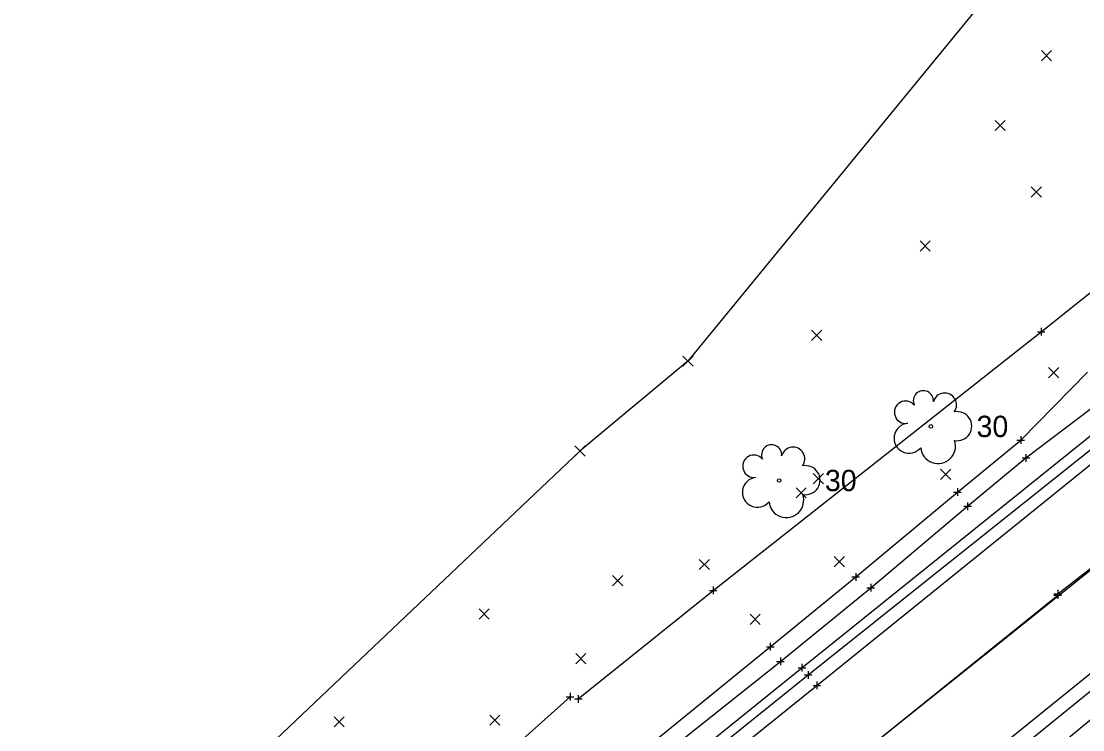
# Model space of a CAD drawing. Extents: x 2184635 to 2185378, y 369880 to 370486.
# Drawn here: x 2184636.1 to 2184775.4, y 369980.5 to 370073.5 of the extents above; entities that cross this region are included whole.
import ezdxf

# ---------------------------------------------------------------- set-up
doc = ezdxf.new("R2010")
doc.units = 0
for name, color, linetype in [('_CIVIL_CONSTRUCTION', 7, 'Continuous'), ('DR_X_Ditch', 7, 'Continuous'), ('GE_X_Alignment', 7, 'Continuous'), ('GE_X_Alignment_100_Distances', 7, 'Continuous'), ('PM_X_CL_Double_Solid', 7, 'Continuous'), ('PM_X_CL_Pass_Proh_Lt', 7, 'Continuous'), ('PM_X_CL_Pass_Proh_Rt', 7, 'Continuous'), ('PM_X_Edge_Line', 7, 'Continuous'), ('PV_X_COP', 7, 'Continuous'), ('PV_X_EOP', 7, 'Continuous'), ('PV_X_Shoulder', 7, 'Continuous'), ('RD_X_Fence', 7, 'Continuous'), ('RD_X_Gate', 7, 'Continuous'), ('RW_X_CL', 7, 'Continuous'), ('SV_X_Break_Lines', 7, 'Continuous'), ('SV_X_Terrain_Boundary', 7, 'Continuous'), ('VG_X_Text', 7, 'Continuous')]:
    doc.layers.add(name, color=color, linetype=linetype)

msp = doc.modelspace()

# ---------------------------------------------------------------- linework, layer by layer
at = {"layer": '_CIVIL_CONSTRUCTION'}
for p, q in [((2184769.93, 370068.28), (2184771.26, 370069.62)), ((2184769.93, 370069.62), (2184771.26, 370068.28)), ((2184763.84, 370059.12), (2184765.18, 370060.46)), ((2184763.84, 370060.46), (2184765.18, 370059.12)), ((2184768.6, 370050.39), (2184769.94, 370051.73)), ((2184768.6, 370051.73), (2184769.94, 370050.39)), ((2184754.01, 370043.31), (2184755.34, 370044.65)), ((2184754.01, 370044.65), (2184755.34, 370043.31)), ((2184739.77, 370031.58), (2184741.1, 370032.91)), ((2184739.77, 370032.91), (2184741.1, 370031.58)), ((2184722.88, 370028.2), (2184724.22, 370029.54)), ((2184722.88, 370029.54), (2184724.22, 370028.2)), ((2184770.88, 370026.69), (2184772.21, 370028.02)), ((2184770.88, 370028.02), (2184772.21, 370026.69)), ((2184708.73, 370016.41), (2184710.07, 370017.75)), ((2184708.73, 370017.75), (2184710.07, 370016.41)), ((2184739.99, 370012.78), (2184741.32, 370014.11)), ((2184739.99, 370014.11), (2184741.32, 370012.78)), ((2184756.69, 370013.35), (2184758.03, 370014.69)), ((2184756.69, 370014.69), (2184758.03, 370013.35)), ((2184737.73, 370010.91), (2184739.06, 370012.24)), ((2184737.73, 370012.24), (2184739.06, 370010.91)), ((2184725.03, 370001.51), (2184726.36, 370002.85)), ((2184725.03, 370002.85), (2184726.36, 370001.51)), ((2184742.74, 370001.89), (2184744.08, 370003.23)), ((2184742.74, 370003.23), (2184744.08, 370001.89)), ((2184713.66, 369999.39), (2184715, 370000.72)), ((2184713.66, 370000.72), (2184715, 369999.39)), ((2184696.14, 369995.01), (2184697.48, 369996.35)), ((2184696.14, 369996.35), (2184697.48, 369995.01)), ((2184731.71, 369994.3), (2184733.04, 369995.64)), ((2184731.71, 369995.64), (2184733.04, 369994.3)), ((2184708.82, 369989.14), (2184710.16, 369990.48)), ((2184708.82, 369990.48), (2184710.16, 369989.14)), ((2184677.12, 369980.85), (2184678.46, 369982.18)), ((2184677.12, 369982.18), (2184678.46, 369980.85)), ((2184697.55, 369981.08), (2184698.88, 369982.42)), ((2184697.55, 369982.42), (2184698.88, 369981.08))]:
    msp.add_line(p, q, dxfattribs=at)
at = {"layer": 'DR_X_Ditch'}
msp.add_lwpolyline([(2184660, 369928.7), (2184683.17, 369946.52), (2184697.64, 369958.49), (2184716.07, 369973.83), (2184735.69, 369989.46), (2184747.53, 369999.12), (2184760.24, 370009.81), (2184767.89, 370016.17), (2184779.93, 370025.29), (2184787.42, 370032.35)], dxfattribs=at)
at = {"layer": 'GE_X_Alignment'}
for centre in [(2184755.42, 370020.3), (2184735.52, 370013.2)]:
    msp.add_circle(centre, 0.24, dxfattribs=at)
for centre, radius, start, end in [((2184754.44, 370023.67), 1.32, 354.0047, 205.9741), ((2184752.11, 370022.16), 1.47, 39.0625, 279.5412), ((2184757.25, 370023.13), 1.55, 323.83, 165.0376), ((2184758.88, 370020.33), 1.91, 259.1453, 101.4596), ((2184752.57, 370018.75), 1.97, 96.1722, 320.5737), ((2184756.37, 370017.69), 2.28, 184.9476, 19.4572), ((2184734.53, 370016.57), 1.32, 354.0047, 205.9741), ((2184737.34, 370016.03), 1.55, 323.83, 165.0376), ((2184732.21, 370015.07), 1.47, 39.0625, 279.5412), ((2184738.98, 370013.24), 1.91, 259.1453, 101.4596), ((2184732.67, 370011.65), 1.97, 96.1722, 320.5737), ((2184736.46, 370010.6), 2.28, 184.9476, 19.4572)]:
    msp.add_arc(centre, radius, start, end, dxfattribs=at)
at = {"layer": 'GE_X_Alignment_100_Distances'}
for points in [[(2185264.32, 370371.31), (2185225.67, 370339.84), (2185186.92, 370307.74), (2185148.74, 370277.09), (2185109.07, 370245.72), (2185070.47, 370214.75), (2185031.04, 370183.42), (2184991.95, 370153.14), (2184952.24, 370122.38), (2184912.89, 370091.69), (2184876.6, 370062.99), (2184874.53, 370062.2), (2184872.48, 370060.47), (2184871.45, 370058.82), (2184869.46, 370057.79), (2184834.83, 370028.95), (2184796.15, 369998.17), (2184773.73, 369979.62), (2184757.69, 369965.83), (2184717.28, 369935.85), (2184678.36, 369904.18)], [(2184659.61, 369925.95), (2184700.37, 369957.79), (2184738.5, 369988.63), (2184777.83, 370020.25), (2184816.43, 370051.35), (2184855.55, 370082.58), (2184897, 370115.36), (2184935.6, 370145.23), (2184944.92, 370153.84), (2184957.87, 370164.57), (2184961.94, 370169.28), (2184974.73, 370179.72), (2184983.89, 370187.22), (2184992.5, 370194.66), (2184997.57, 370200.25)]]:
    msp.add_lwpolyline(points, dxfattribs=at)
at = {"layer": 'PM_X_CL_Double_Solid'}
msp.add_lwpolyline([(2184667.89, 369914.6), (2184708.44, 369946.75), (2184746.44, 369977.52), (2184772.08, 369998.17)], dxfattribs=at)
at = {"layer": 'PM_X_CL_Pass_Proh_Lt'}
msp.add_lwpolyline([(2185262.14, 370374.2), (2185223.7, 370342.03), (2185185.18, 370310.66), (2185146.68, 370279.54), (2185107.74, 370248.35), (2185068.5, 370216.96), (2185029.05, 370186.04), (2184989.47, 370156.28), (2184949.89, 370125.37), (2184910.77, 370094.56), (2184870.98, 370063.53), (2184832.08, 370032.4), (2184793.2, 370001.49), (2184754.34, 369970.02), (2184715.12, 369938.51), (2184676.14, 369907.22)], dxfattribs=at)
at = {"layer": 'PM_X_CL_Pass_Proh_Rt'}
msp.add_lwpolyline([(2184772.08, 369998.33), (2184786.36, 370009.44), (2184824.96, 370040.26), (2184864.24, 370071.89), (2184905.97, 370104.8), (2184943.4, 370134), (2184983.48, 370165.21), (2185020.26, 370194.47), (2185061.22, 370226.63), (2185099.74, 370257.78), (2185139.18, 370289.51), (2185177.35, 370320.31), (2185216.05, 370351.8), (2185254.73, 370383.45)], dxfattribs=at)
at = {"layer": 'PM_X_Edge_Line'}
msp.add_lwpolyline([(2184661.52, 369922.95), (2184702.12, 369955.42), (2184740.46, 369986.31), (2184779.79, 370018.04), (2184818.42, 370048.83), (2184857.46, 370080.19), (2184899.14, 370112.8), (2184937.36, 370142.73), (2184976.78, 370173.64), (2185013.23, 370203.93), (2185054.74, 370235.21), (2185093.13, 370266.2), (2185132.9, 370298.21), (2185170.88, 370328.99), (2185209.71, 370360.44), (2185248.24, 370392.05)], dxfattribs=at)
at = {"layer": 'PV_X_COP'}
msp.add_lwpolyline([(2184667.94, 369914.54), (2184708.44, 369946.75), (2184746.44, 369977.52), (2184786.36, 370009.44), (2184824.96, 370040.26), (2184864.24, 370071.89), (2184905.97, 370104.8), (2184943.4, 370134), (2184983.48, 370165.21), (2185020.26, 370194.47), (2185061.22, 370226.63), (2185099.74, 370257.78), (2185139.18, 370289.51), (2185177.35, 370320.31), (2185216.05, 370351.8), (2185254.68, 370383.2)], dxfattribs=at)
at = {"layer": 'PV_X_EOP'}
for points in [[(2184661.56, 369922.86), (2184702.12, 369955.42), (2184740.46, 369986.31), (2184779.79, 370018.04), (2184818.42, 370048.83), (2184857.46, 370080.19), (2184899.14, 370112.8), (2184937.36, 370142.73), (2184976.78, 370173.64), (2185013.23, 370203.93), (2185054.74, 370235.21), (2185093.13, 370266.2), (2185132.9, 370298.21), (2185170.88, 370328.99), (2185209.71, 370360.44), (2185248.18, 370392.04)], [(2185262.15, 370374.26), (2185223.7, 370342.03), (2185185.18, 370310.66), (2185146.68, 370279.54), (2185107.74, 370248.35), (2185068.5, 370216.96), (2185029.05, 370186.04), (2184989.47, 370156.28), (2184949.89, 370125.37), (2184910.77, 370094.56), (2184870.98, 370063.53), (2184832.08, 370032.4), (2184793.2, 370001.49), (2184754.34, 369970.02), (2184715.12, 369938.51), (2184676.22, 369907.13)]]:
    msp.add_lwpolyline(points, dxfattribs=at)
at = {"layer": 'PV_X_Shoulder'}
for points in [[(2184660.62, 369924.65), (2184701.18, 369956.99), (2184739.31, 369987.69), (2184778.66, 370019.08), (2184817.14, 370050.2), (2184856.42, 370081.4), (2184897.96, 370114.28), (2184936.32, 370143.73), (2184975.81, 370174.82), (2184986.61, 370184.31), (2184994.08, 370192.55), (2185011.04, 370206.65), (2185033.17, 370224.29), (2185051.81, 370238.9), (2185062.89, 370246.96), (2185064.96, 370248), (2185067.33, 370248.11), (2185092.06, 370267.24), (2185132, 370299.51), (2185169.97, 370330.25), (2185208.84, 370361.61), (2185247.24, 370392.98)], [(2185263.13, 370373.08), (2185224.63, 370341.08), (2185185.98, 370309.59), (2185147.25, 370278.48), (2185108.32, 370247.41), (2185069.3, 370216.14), (2185029.87, 370185.15), (2184990.36, 370154.9), (2184951.08, 370123.83), (2184911.78, 370093.32), (2184872.08, 370062.16), (2184833.34, 370030.96), (2184794.18, 369999.97), (2184755.6, 369968.65), (2184716.02, 369937.32), (2184677.49, 369905.63)]]:
    msp.add_lwpolyline(points, dxfattribs=at)
at = {"layer": 'RD_X_Fence'}
msp.add_lwpolyline([(2184709.16, 369984.54), (2184726.86, 369998.78), (2184769.9, 370032.73), (2184797.39, 370054.67), (2184814.48, 370067.87), (2184833.19, 370083.12), (2184887.17, 370125.99), (2184905.93, 370138.5)], dxfattribs=at)
at = {"layer": 'RD_X_Gate'}
msp.add_lwpolyline([(2184699.38, 369977.01), (2184708.09, 369984.81)], dxfattribs=at)
at = {"layer": 'RW_X_CL'}
for p, q in [((2184769.4, 370032.73), (2184770.4, 370032.73)), ((2184769.9, 370033.23), (2184769.9, 370032.23)), ((2184769.9, 370032.73), (2184769.9, 370032.73)), ((2184766.71, 370018.51), (2184767.71, 370018.51)), ((2184767.21, 370019.01), (2184767.21, 370018.01)), ((2184767.21, 370018.51), (2184767.21, 370018.51)), ((2184767.89, 370016.67), (2184767.89, 370015.67)), ((2184767.39, 370016.17), (2184768.39, 370016.17)), ((2184767.89, 370016.17), (2184767.89, 370016.17)), ((2184758.41, 370011.68), (2184759.41, 370011.68)), ((2184758.91, 370012.18), (2184758.91, 370011.18)), ((2184758.91, 370011.68), (2184758.91, 370011.68)), ((2184759.74, 370009.81), (2184760.74, 370009.81)), ((2184760.24, 370010.31), (2184760.24, 370009.31)), ((2184760.24, 370009.81), (2184760.24, 370009.81)), ((2184745.06, 370000.54), (2184746.06, 370000.54)), ((2184745.56, 370001.04), (2184745.56, 370000.04)), ((2184745.56, 370000.54), (2184745.56, 370000.54)), ((2184726.36, 369998.78), (2184727.36, 369998.78)), ((2184726.86, 369999.28), (2184726.86, 369998.28)), ((2184726.86, 369998.78), (2184726.86, 369998.78)), ((2184747.03, 369999.12), (2184748.03, 369999.12)), ((2184747.53, 369999.62), (2184747.53, 369998.62)), ((2184747.53, 369999.12), (2184747.53, 369999.12)), ((2184772.08, 369998.83), (2184772.08, 369997.83)), ((2184772.08, 369998.67), (2184772.08, 369997.67)), ((2184771.58, 369998.33), (2184772.58, 369998.33)), ((2184771.58, 369998.17), (2184772.58, 369998.17)), ((2184772.08, 369998.33), (2184772.08, 369998.33)), ((2184772.08, 369998.17), (2184772.08, 369998.17)), ((2184734.36, 369991.88), (2184734.36, 369990.88)), ((2184733.86, 369991.38), (2184734.86, 369991.38)), ((2184734.36, 369991.38), (2184734.36, 369991.38)), ((2184735.19, 369989.46), (2184736.19, 369989.46)), ((2184735.69, 369989.96), (2184735.69, 369988.96)), ((2184735.69, 369989.46), (2184735.69, 369989.46)), ((2184738.5, 369989.13), (2184738.5, 369988.13)), ((2184738, 369988.63), (2184739, 369988.63)), ((2184738.5, 369988.63), (2184738.5, 369988.63)), ((2184738.81, 369987.69), (2184739.81, 369987.69)), ((2184739.31, 369988.19), (2184739.31, 369987.19)), ((2184739.31, 369987.69), (2184739.31, 369987.69)), ((2184739.96, 369986.31), (2184740.96, 369986.31)), ((2184739.96, 369986.31), (2184740.96, 369986.31)), ((2184740.46, 369986.81), (2184740.46, 369985.81)), ((2184740.46, 369986.81), (2184740.46, 369985.81)), ((2184740.46, 369986.31), (2184740.46, 369986.31)), ((2184740.46, 369986.31), (2184740.46, 369986.31)), ((2184707.59, 369984.81), (2184708.59, 369984.81)), ((2184708.09, 369985.31), (2184708.09, 369984.31)), ((2184708.09, 369984.81), (2184708.09, 369984.81)), ((2184709.16, 369985.04), (2184709.16, 369984.04)), ((2184708.66, 369984.54), (2184709.66, 369984.54)), ((2184709.16, 369984.54), (2184709.16, 369984.54))]:
    msp.add_line(p, q, dxfattribs=at)
at = {"layer": 'SV_X_Break_Lines'}
msp.add_lwpolyline([(2184658.56, 369930.26), (2184681.6, 369948.01), (2184695.72, 369960.53), (2184715.28, 369975.82), (2184734.36, 369991.38), (2184745.56, 370000.54), (2184758.91, 370011.68), (2184767.21, 370018.51), (2184775.97, 370027.43)], dxfattribs=at)
at = {"layer": 'SV_X_Terrain_Boundary'}
msp.add_lwpolyline([(2185048.79, 370280.75), (2184981.84, 370244.63), (2184966.76, 370227.41), (2184901.88, 370166.35), (2184859.95, 370200.01), (2184846.28, 370205.14), (2184825.04, 370216.07), (2184786.25, 370161.28), (2184768.88, 370142.96), (2184755.89, 370127.05), (2184768.66, 370083.99), (2184723.55, 370028.87), (2184709.4, 370017.08), (2184650.83, 369961.55), (2184636.07, 369950.04)], dxfattribs=at)

# ---------------------------------------------------------------- texts
at = {"layer": 'VG_X_Text'}
for p in [(2184761.42, 370018.9), (2184741.52, 370011.8)]:
    msp.add_text('30', height=2.8, dxfattribs=at).set_placement(p)

doc.saveas('drawing.dxf')
